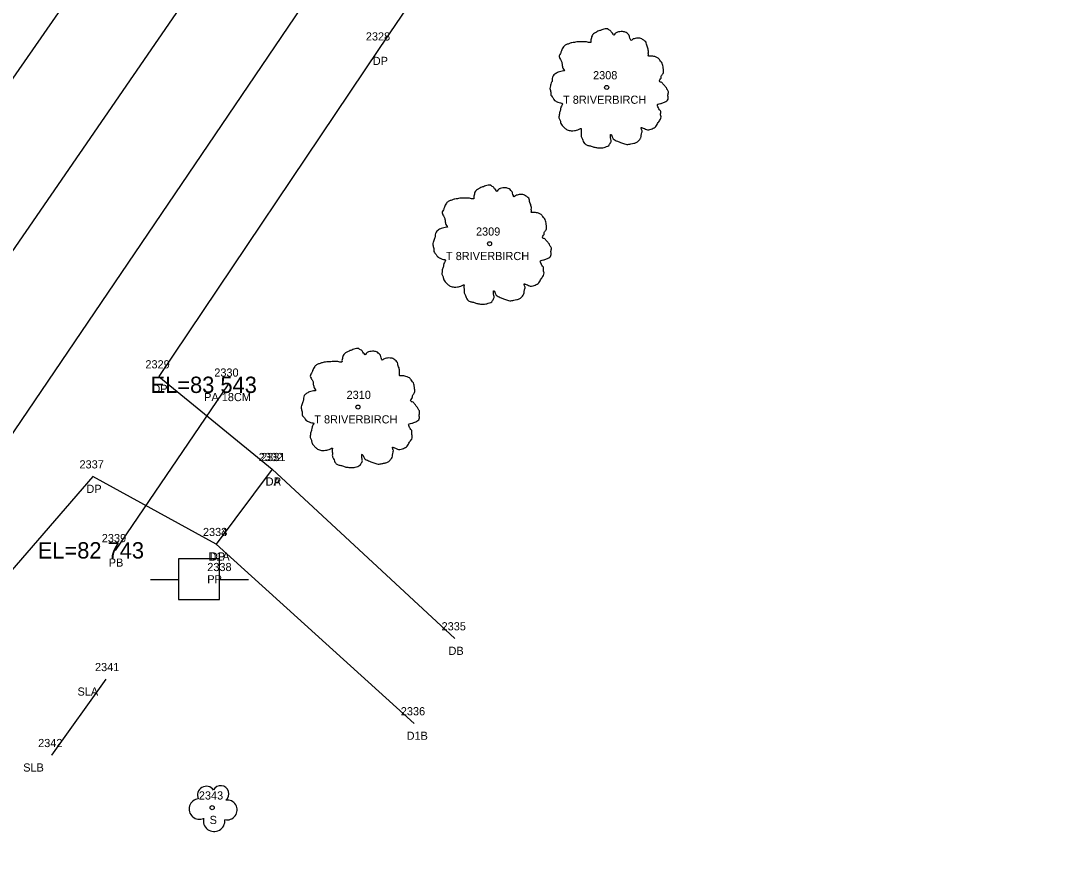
# Model space of a CAD drawing. Extents: x 2266664 to 2272542, y 716533 to 724777.
# Drawn here: x 2271445.4 to 2271573.7, y 723355.6 to 723459.5 of the extents above; entities that cross this region are included whole.
import ezdxf

# ---------------------------------------------------------------- set-up
doc = ezdxf.new("R2010")
doc.units = 0
for name, color, linetype in [('RD_EX_DR_Pipe', 7, 'Continuous'), ('RD_EX_DR_Pipe_txCode', 7, 'Continuous'), ('RD_EX_Driveway', 7, 'Continuous'), ('RD_EX_Driveway_txCode', 7, 'Continuous'), ('RD_EX_Road', 7, 'Continuous'), ('RD_EX_UT', 7, 'Continuous'), ('RD_EX_UT_txCode', 7, 'Continuous'), ('RD_EX_VEG', 7, 'Continuous'), ('RD_EX_VEG_txCode', 7, 'Continuous'), ('RD_HC_Cl', 7, 'Continuous'), ('RD_SMD_Locator', 7, 'Continuous'), ('RD_TX_Pipe_ElevEX', 7, 'Continuous')]:
    doc.layers.add(name, color=color, linetype=linetype)

msp = doc.modelspace()

# ---------------------------------------------------------------- linework, layer by layer
at = {"layer": 'RD_EX_DR_Pipe'}
msp.add_line((2271470.71, 723414.93), (2271456.9, 723394.66), dxfattribs=at)
at = {"layer": 'RD_EX_Driveway'}
for p, q in [((2271476.12, 723404.59), (2271498.49, 723383.86)), ((2271469.28, 723395.41), (2271493.52, 723373.46))]:
    msp.add_line(p, q, dxfattribs=at)
msp.add_lwpolyline([(2271561.71, 723471.33), (2271533.81, 723491.49), (2271519.19, 723500.22), (2271489.22, 723456.09), (2271462.24, 723415.94), (2271476.12, 723404.59), (2271469.28, 723395.41), (2271454.17, 723403.69), (2271433.28, 723379.57), (2271407.1, 723356.2)], dxfattribs=at)
at = {"layer": 'RD_EX_Road'}
for points in [[(2271604.53, 723684.77), (2271550.65, 723606.61), (2271518.33, 723560.15), (2271484.03, 723509.64), (2271377.45, 723356.07), (2271354.74, 723322.34), (2271292.52, 723232.43), (2271237.2, 723151.69), (2271183.29, 723072.86), (2271144.18, 723016.57), (2271140.21, 723010.22), (2271130.75, 722996.02)], [(2271614.21, 723655.35), (2271570.62, 723593.07), (2271532.38, 723537.1), (2271480.53, 723462.42), (2271443.77, 723408.17), (2271407.1, 723356.2), (2271374.69, 723308.79), (2271312.42, 723217.53), (2271256.65, 723136.94), (2271202.38, 723058.06), (2271164.68, 723002.43), (2271160.3, 722996.7), (2271150.37, 722982.5)]]:
    msp.add_lwpolyline(points, dxfattribs=at)
at = {"layer": 'RD_EX_UT'}
for p, q in [((2271469.67, 723393.63), (2271464.67, 723393.63)), ((2271464.67, 723393.63), (2271464.67, 723388.63)), ((2271469.67, 723388.63), (2271469.67, 723393.63)), ((2271461.24, 723391.07), (2271464.71, 723391.07)), ((2271469.6, 723391.07), (2271473.24, 723391.07)), ((2271464.67, 723388.63), (2271469.67, 723388.63))]:
    msp.add_line(p, q, dxfattribs=at)
at = {"layer": 'RD_EX_VEG'}
msp.add_line((2271455.78, 723378.87), (2271449.11, 723369.57), dxfattribs=at)
for centre, radius in [((2271517.07, 723451.34), 0.25), ((2271517.06, 723451.32), 0.0001), ((2271502.74, 723432.2), 0.25), ((2271502.73, 723432.18), 0.0001), ((2271486.62, 723412.2), 0.25), ((2271486.6, 723412.18), 0.0001), ((2271468.78, 723363.15), 0.25)]:
    msp.add_circle(centre, radius, dxfattribs=at)
for centre, radius, start, end in [((2271468.06, 723364.69), 1.08, 34.9763, 204.756), ((2271469.82, 723364.85), 0.995, 308.7626, 152.0467), ((2271467.22, 723362.99), 1.26, 96.4518, 294.734), ((2271470.62, 723362.87), 1.22, 256.5667, 98.1046), ((2271469.02, 723361.55), 1.32, 166.8827, 5.7589)]:
    msp.add_arc(centre, radius, start, end, dxfattribs=at)
for points in [[(2271517.2, 723458.51), (2271516.9, 723458.53), (2271516.58, 723458.43), (2271516.33, 723458.33), (2271516.1, 723458.26), (2271515.88, 723458.16), (2271515.58, 723457.98), (2271515.35, 723457.78), (2271515.23, 723457.53), (2271515.18, 723457.31), (2271515.13, 723457.03), (2271515.13, 723456.86), (2271515, 723456.83), (2271514.85, 723456.86), (2271514.6, 723456.93), (2271514.35, 723456.93), (2271514.1, 723456.93), (2271513.75, 723456.91), (2271513.4, 723456.91), (2271513.13, 723456.86), (2271512.8, 723456.81), (2271512.43, 723456.68), (2271512.08, 723456.56), (2271511.78, 723456.31), (2271511.53, 723455.83), (2271511.4, 723455.48), (2271511.25, 723455.23), (2271511.4, 723454.78), (2271511.58, 723454.43), (2271511.6, 723454.23), (2271511.68, 723453.81), (2271511.78, 723453.58), (2271511.9, 723453.38), (2271511.83, 723453.36), (2271511.45, 723453.31), (2271511.15, 723453.21), (2271510.73, 723452.98), (2271510.5, 723452.76), (2271510.4, 723452.43), (2271510.38, 723452.08), (2271510.28, 723451.89), (2271510.2, 723451.61), (2271510.18, 723451.54), (2271510.13, 723451.21), (2271510.23, 723450.76), (2271510.25, 723450.41), (2271510.38, 723450.19), (2271510.53, 723450.01), (2271510.7, 723449.76), (2271511.1, 723449.54), (2271511.43, 723449.44), (2271511.63, 723449.41), (2271511.45, 723448.91), (2271511.4, 723448.56), (2271511.28, 723448.16), (2271511.28, 723448.09), (2271511.23, 723447.61), (2271511.38, 723447.29), (2271511.45, 723446.91), (2271511.63, 723446.69), (2271511.9, 723446.39), (2271512.23, 723446.16), (2271512.73, 723446.04), (2271513.13, 723446.06), (2271513.7, 723446.24), (2271513.95, 723446.31), (2271513.93, 723446.14), (2271513.95, 723445.76), (2271513.95, 723445.34), (2271514.1, 723445.01), (2271514.2, 723444.74), (2271514.35, 723444.49), (2271514.68, 723444.26), (2271515.08, 723444.19), (2271515.5, 723444.04), (2271515.95, 723443.96), (2271516.45, 723443.94), (2271517.05, 723444.09), (2271517.33, 723444.21), (2271517.43, 723444.39), (2271517.63, 723444.76), (2271517.58, 723444.99), (2271517.6, 723445.59), (2271517.7, 723445.41), (2271517.88, 723445.06), (2271518.38, 723444.76), (2271518.78, 723444.59), (2271519.25, 723444.44), (2271519.55, 723444.36), (2271520.02, 723444.44), (2271520.4, 723444.51), (2271520.77, 723444.64), (2271521.07, 723444.91), (2271521.25, 723445.19), (2271521.3, 723445.46), (2271521.37, 723445.84), (2271521.42, 723446.01)], [(2271521.42, 723446.01), (2271521.35, 723446.19), (2271521.3, 723446.44), (2271521.37, 723446.41), (2271521.55, 723446.36), (2271521.82, 723446.24), (2271522.05, 723446.16), (2271522.37, 723446.19), (2271522.65, 723446.29), (2271523.1, 723446.56), (2271523.37, 723447.04), (2271523.65, 723447.44), (2271523.72, 723447.76), (2271523.67, 723447.99), (2271523.65, 723448.49), (2271523.45, 723448.74), (2271523.4, 723448.86), (2271523.3, 723449.26), (2271523.37, 723449.31), (2271523.65, 723449.36), (2271524.02, 723449.49), (2271524.3, 723449.61), (2271524.52, 723449.79), (2271524.6, 723450.01), (2271524.57, 723450.41), (2271524.62, 723450.81), (2271524.55, 723450.96), (2271524.45, 723451.11), (2271524.37, 723451.31), (2271524.22, 723451.46), (2271524.12, 723451.61), (2271524.02, 723451.71), (2271523.9, 723451.86), (2271523.72, 723451.98), (2271523.57, 723452.03), (2271523.52, 723452.18), (2271523.67, 723452.38), (2271523.72, 723452.48), (2271523.75, 723452.71), (2271523.97, 723453.06), (2271524.02, 723453.46), (2271523.97, 723453.88), (2271523.92, 723454.16), (2271523.77, 723454.43), (2271523.57, 723454.68), (2271523.45, 723454.86), (2271523.27, 723454.98), (2271522.95, 723455.11), (2271522.7, 723455.16), (2271522.35, 723455.16), (2271522.15, 723455.21), (2271522.17, 723455.26), (2271522.17, 723455.41), (2271522.17, 723455.68), (2271522.1, 723456.13), (2271521.95, 723456.63), (2271521.95, 723456.66), (2271521.85, 723456.91), (2271521.62, 723457.11), (2271521.45, 723457.21), (2271521.25, 723457.33), (2271521, 723457.36), (2271520.7, 723457.36), (2271520.42, 723457.31), (2271520.22, 723457.21), (2271520.05, 723457.08), (2271519.97, 723457.23), (2271519.88, 723457.53), (2271519.83, 723457.68), (2271519.68, 723457.86), (2271519.45, 723458.06), (2271519, 723458.18), (2271518.38, 723458.11), (2271518.08, 723457.91), (2271517.93, 723457.73), (2271517.88, 723457.86), (2271517.68, 723458.06), (2271517.58, 723458.23), (2271517.4, 723458.36), (2271517.25, 723458.46), (2271517.15, 723458.51)], [(2271502.87, 723439.37), (2271502.57, 723439.39), (2271502.25, 723439.29), (2271502, 723439.19), (2271501.77, 723439.12), (2271501.55, 723439.02), (2271501.25, 723438.84), (2271501.02, 723438.64), (2271500.9, 723438.39), (2271500.85, 723438.17), (2271500.8, 723437.89), (2271500.8, 723437.72), (2271500.67, 723437.69), (2271500.52, 723437.72), (2271500.27, 723437.79), (2271500.02, 723437.79), (2271499.78, 723437.79), (2271499.43, 723437.77), (2271499.08, 723437.77), (2271498.8, 723437.72), (2271498.48, 723437.67), (2271498.1, 723437.54), (2271497.75, 723437.42), (2271497.45, 723437.17), (2271497.2, 723436.69), (2271497.08, 723436.34), (2271496.93, 723436.09), (2271497.08, 723435.64), (2271497.25, 723435.29), (2271497.28, 723435.09), (2271497.35, 723434.67), (2271497.45, 723434.44), (2271497.58, 723434.24), (2271497.5, 723434.22), (2271497.13, 723434.17), (2271496.83, 723434.07), (2271496.4, 723433.84), (2271496.18, 723433.62), (2271496.08, 723433.29), (2271496.05, 723432.94), (2271495.95, 723432.74), (2271495.88, 723432.47), (2271495.85, 723432.39), (2271495.8, 723432.07), (2271495.9, 723431.62), (2271495.93, 723431.27), (2271496.05, 723431.04), (2271496.2, 723430.87), (2271496.38, 723430.62), (2271496.78, 723430.39), (2271497.1, 723430.29), (2271497.3, 723430.27), (2271497.13, 723429.77), (2271497.08, 723429.42), (2271496.95, 723429.02), (2271496.95, 723428.94), (2271496.9, 723428.47), (2271497.05, 723428.15), (2271497.13, 723427.77), (2271497.3, 723427.55), (2271497.58, 723427.25), (2271497.9, 723427.02), (2271498.4, 723426.9), (2271498.8, 723426.92), (2271499.38, 723427.1), (2271499.63, 723427.17), (2271499.6, 723427), (2271499.63, 723426.62), (2271499.63, 723426.2), (2271499.78, 723425.87), (2271499.88, 723425.6), (2271500.02, 723425.35), (2271500.35, 723425.12), (2271500.75, 723425.05), (2271501.17, 723424.9), (2271501.62, 723424.82), (2271502.12, 723424.8), (2271502.72, 723424.95), (2271503, 723425.07), (2271503.1, 723425.25), (2271503.3, 723425.62), (2271503.25, 723425.85), (2271503.27, 723426.45), (2271503.37, 723426.27), (2271503.55, 723425.92), (2271504.05, 723425.62), (2271504.45, 723425.45), (2271504.92, 723425.3), (2271505.22, 723425.22), (2271505.7, 723425.3), (2271506.07, 723425.37), (2271506.45, 723425.5), (2271506.75, 723425.77), (2271506.92, 723426.05), (2271506.97, 723426.32), (2271507.05, 723426.7), (2271507.1, 723426.87)], [(2271507.1, 723426.87), (2271507.02, 723427.05), (2271506.97, 723427.3), (2271507.05, 723427.27), (2271507.22, 723427.22), (2271507.5, 723427.1), (2271507.72, 723427.02), (2271508.05, 723427.05), (2271508.32, 723427.15), (2271508.77, 723427.42), (2271509.05, 723427.9), (2271509.32, 723428.3), (2271509.4, 723428.62), (2271509.35, 723428.84), (2271509.32, 723429.34), (2271509.12, 723429.59), (2271509.07, 723429.72), (2271508.97, 723430.12), (2271509.05, 723430.17), (2271509.32, 723430.22), (2271509.7, 723430.34), (2271509.97, 723430.47), (2271510.2, 723430.64), (2271510.27, 723430.87), (2271510.25, 723431.27), (2271510.3, 723431.67), (2271510.22, 723431.82), (2271510.12, 723431.97), (2271510.05, 723432.17), (2271509.9, 723432.32), (2271509.8, 723432.47), (2271509.7, 723432.57), (2271509.57, 723432.72), (2271509.4, 723432.84), (2271509.25, 723432.89), (2271509.2, 723433.04), (2271509.35, 723433.24), (2271509.4, 723433.34), (2271509.42, 723433.57), (2271509.65, 723433.92), (2271509.7, 723434.32), (2271509.65, 723434.74), (2271509.6, 723435.02), (2271509.45, 723435.29), (2271509.25, 723435.54), (2271509.12, 723435.72), (2271508.95, 723435.84), (2271508.62, 723435.97), (2271508.37, 723436.02), (2271508.02, 723436.02), (2271507.82, 723436.07), (2271507.85, 723436.12), (2271507.85, 723436.27), (2271507.85, 723436.54), (2271507.77, 723436.99), (2271507.62, 723437.49), (2271507.62, 723437.52), (2271507.52, 723437.77), (2271507.3, 723437.97), (2271507.12, 723438.07), (2271506.92, 723438.19), (2271506.67, 723438.22), (2271506.37, 723438.22), (2271506.1, 723438.17), (2271505.9, 723438.07), (2271505.72, 723437.94), (2271505.65, 723438.09), (2271505.55, 723438.39), (2271505.5, 723438.54), (2271505.35, 723438.72), (2271505.12, 723438.92), (2271504.67, 723439.04), (2271504.05, 723438.97), (2271503.75, 723438.77), (2271503.6, 723438.59), (2271503.55, 723438.72), (2271503.35, 723438.92), (2271503.25, 723439.09), (2271503.07, 723439.22), (2271502.92, 723439.32), (2271502.82, 723439.37)], [(2271486.75, 723419.36), (2271486.45, 723419.39), (2271486.12, 723419.29), (2271485.87, 723419.19), (2271485.65, 723419.11), (2271485.42, 723419.01), (2271485.12, 723418.84), (2271484.9, 723418.64), (2271484.77, 723418.39), (2271484.72, 723418.16), (2271484.67, 723417.89), (2271484.67, 723417.71), (2271484.55, 723417.69), (2271484.4, 723417.71), (2271484.15, 723417.79), (2271483.9, 723417.79), (2271483.65, 723417.79), (2271483.3, 723417.76), (2271482.95, 723417.76), (2271482.67, 723417.71), (2271482.35, 723417.66), (2271481.98, 723417.54), (2271481.63, 723417.41), (2271481.33, 723417.16), (2271481.08, 723416.69), (2271480.95, 723416.34), (2271480.8, 723416.09), (2271480.95, 723415.64), (2271481.13, 723415.29), (2271481.15, 723415.09), (2271481.23, 723414.66), (2271481.33, 723414.44), (2271481.45, 723414.24), (2271481.38, 723414.21), (2271481, 723414.16), (2271480.7, 723414.06), (2271480.28, 723413.84), (2271480.05, 723413.61), (2271479.95, 723413.29), (2271479.93, 723412.94), (2271479.83, 723412.74), (2271479.75, 723412.47), (2271479.73, 723412.39), (2271479.68, 723412.07), (2271479.78, 723411.62), (2271479.8, 723411.27), (2271479.93, 723411.04), (2271480.08, 723410.87), (2271480.25, 723410.62), (2271480.65, 723410.39), (2271480.98, 723410.29), (2271481.18, 723410.27), (2271481, 723409.77), (2271480.95, 723409.42), (2271480.83, 723409.02), (2271480.83, 723408.94), (2271480.78, 723408.47), (2271480.93, 723408.14), (2271481, 723407.77), (2271481.18, 723407.54), (2271481.45, 723407.24), (2271481.78, 723407.02), (2271482.28, 723406.89), (2271482.67, 723406.92), (2271483.25, 723407.09), (2271483.5, 723407.17), (2271483.47, 723406.99), (2271483.5, 723406.62), (2271483.5, 723406.19), (2271483.65, 723405.87), (2271483.75, 723405.59), (2271483.9, 723405.34), (2271484.22, 723405.12), (2271484.62, 723405.04), (2271485.05, 723404.89), (2271485.5, 723404.82), (2271486, 723404.79), (2271486.6, 723404.94), (2271486.87, 723405.07), (2271486.97, 723405.24), (2271487.17, 723405.62), (2271487.12, 723405.84), (2271487.15, 723406.44), (2271487.25, 723406.27), (2271487.42, 723405.92), (2271487.92, 723405.62), (2271488.32, 723405.44), (2271488.8, 723405.29), (2271489.1, 723405.22), (2271489.57, 723405.29), (2271489.95, 723405.37), (2271490.32, 723405.49), (2271490.62, 723405.77), (2271490.8, 723406.04), (2271490.85, 723406.32), (2271490.92, 723406.69), (2271490.97, 723406.87)], [(2271490.97, 723406.87), (2271490.9, 723407.04), (2271490.85, 723407.29), (2271490.92, 723407.27), (2271491.1, 723407.22), (2271491.37, 723407.09), (2271491.6, 723407.02), (2271491.92, 723407.04), (2271492.2, 723407.14), (2271492.65, 723407.42), (2271492.92, 723407.89), (2271493.2, 723408.29), (2271493.27, 723408.62), (2271493.22, 723408.84), (2271493.2, 723409.34), (2271493, 723409.59), (2271492.95, 723409.72), (2271492.85, 723410.12), (2271492.92, 723410.17), (2271493.2, 723410.22), (2271493.57, 723410.34), (2271493.85, 723410.47), (2271494.07, 723410.64), (2271494.14, 723410.87), (2271494.12, 723411.27), (2271494.17, 723411.67), (2271494.09, 723411.82), (2271493.99, 723411.97), (2271493.92, 723412.17), (2271493.77, 723412.32), (2271493.67, 723412.47), (2271493.57, 723412.57), (2271493.45, 723412.72), (2271493.27, 723412.84), (2271493.12, 723412.89), (2271493.07, 723413.04), (2271493.22, 723413.24), (2271493.27, 723413.34), (2271493.3, 723413.56), (2271493.52, 723413.91), (2271493.57, 723414.31), (2271493.52, 723414.74), (2271493.47, 723415.01), (2271493.32, 723415.29), (2271493.12, 723415.54), (2271493, 723415.71), (2271492.82, 723415.84), (2271492.5, 723415.96), (2271492.25, 723416.01), (2271491.9, 723416.01), (2271491.7, 723416.06), (2271491.72, 723416.11), (2271491.72, 723416.26), (2271491.72, 723416.54), (2271491.65, 723416.99), (2271491.5, 723417.49), (2271491.5, 723417.51), (2271491.4, 723417.76), (2271491.17, 723417.96), (2271491, 723418.06), (2271490.8, 723418.19), (2271490.55, 723418.21), (2271490.25, 723418.21), (2271489.97, 723418.16), (2271489.77, 723418.06), (2271489.6, 723417.94), (2271489.52, 723418.09), (2271489.42, 723418.39), (2271489.37, 723418.54), (2271489.22, 723418.71), (2271489, 723418.91), (2271488.55, 723419.04), (2271487.92, 723418.96), (2271487.62, 723418.76), (2271487.47, 723418.59), (2271487.42, 723418.71), (2271487.22, 723418.91), (2271487.12, 723419.09), (2271486.95, 723419.21), (2271486.8, 723419.31), (2271486.7, 723419.36)]]:
    msp.add_spline(points, degree=3, dxfattribs=at)
at = {"layer": 'RD_HC_Cl'}
msp.add_line((2267342.91, 717471.2), (2272360.46, 724762.59), dxfattribs=at)
at = {"layer": 'RD_SMD_Locator'}
for centre in [(2271489.22, 723456.09), (2271462.24, 723415.94), (2271470.71, 723414.93), (2271454.17, 723403.69), (2271476.12, 723404.59), (2271476.12, 723404.59), (2271456.9, 723394.66), (2271469.28, 723395.41), (2271469.28, 723395.41), (2271498.49, 723383.86), (2271455.78, 723378.87), (2271493.52, 723373.46), (2271449.11, 723369.57)]:
    msp.add_circle(centre, 0.001, dxfattribs=at)

# ---------------------------------------------------------------- texts
at = {"layer": 'RD_EX_DR_Pipe_txCode'}
for s, p in [('2330', (2271469.04, 723415.93)), ('PA 18CM', (2271467.8, 723412.93)), ('2339', (2271455.27, 723395.66)), ('PB', (2271456.12, 723392.66))]:
    msp.add_text(s, height=1, dxfattribs=at).set_placement(p)
at = {"layer": 'RD_EX_Driveway_txCode'}
for s, p in [('2328', (2271487.59, 723457.09)), ('DP', (2271488.44, 723454.09)), ('2329', (2271460.61, 723416.94)), ('DP', (2271461.46, 723413.94)), ('2332', (2271474.49, 723405.59)), ('2331', (2271474.77, 723405.59)), ('2337', (2271452.54, 723404.69)), ('DA', (2271475.32, 723402.59)), ('DP', (2271475.34, 723402.59)), ('DP', (2271453.39, 723401.69)), ('2333', (2271467.65, 723396.41)), ('2334', (2271467.65, 723396.41)), ('D1A', (2271468.32, 723393.41)), ('DP', (2271468.5, 723393.41)), ('2335', (2271496.86, 723384.86)), ('DB', (2271497.71, 723381.86)), ('2336', (2271491.87, 723374.46)), ('D1B', (2271492.58, 723371.46))]:
    msp.add_text(s, height=1, dxfattribs=at).set_placement(p)
at = {"layer": 'RD_EX_UT_txCode'}
for s, p in [('2338', (2271468.18, 723392.12)), ('PP', (2271468.18, 723390.62))]:
    msp.add_text(s, height=1, dxfattribs=at).set_placement(p)
at = {"layer": 'RD_EX_VEG_txCode'}
for s, p in [('2308', (2271515.4, 723452.34)), ('T 8RIVERBIRCH', (2271511.73, 723449.34)), ('2309', (2271501.07, 723433.2)), ('T 8RIVERBIRCH', (2271497.4, 723430.2)), ('2310', (2271485.23, 723413.2)), ('T 8RIVERBIRCH', (2271481.28, 723410.2)), ('2341', (2271454.44, 723379.87)), ('SLA', (2271452.3, 723376.87)), ('2342', (2271447.48, 723370.57)), ('SLB', (2271445.65, 723367.57)), ('2343', (2271467.15, 723364.15)), ('S', (2271468.47, 723361.15))]:
    msp.add_text(s, height=1, dxfattribs=at).set_placement(p)
at = {"layer": 'RD_TX_Pipe_ElevEX'}
for s, p in [('EL=83 543  ', (2271461.24, 723413.93)), ('EL=82 743  ', (2271447.43, 723393.66))]:
    msp.add_text(s, height=2, dxfattribs=at).set_placement(p)

doc.saveas('drawing.dxf')
